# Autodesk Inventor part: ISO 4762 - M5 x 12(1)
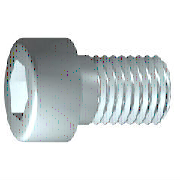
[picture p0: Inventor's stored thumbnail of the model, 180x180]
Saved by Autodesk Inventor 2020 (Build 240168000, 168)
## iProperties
Created: 2019-01
Part Number: ISO 4762 - M5 x 12(1)
Material: Nerezová ocel 440C
Description: Šroub s válcovou hlavou s vnitřním šestihranem
Document SubType Name: Modeling
Standard: ISO 4762
Designer: doma
Standard Revision: Fourth edition 2004-03-01
Standards Organization: ISO
Language: cs-CZ
Size Designation: M5 x 12
Categories: <MemberInstance><Categories><Category DisplayName="Spojovací materiál" InternalName="e4da775c-781d-43d5-af7c-5136215cf5a6" Mnemonic="FSTN"><Category DisplayName
Density: 7.75 g/cm^3
Appearance: Pololeštěná
IsCustomPart: 0
Author: doma
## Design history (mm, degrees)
sketch "Náčrt1"
  geometry: L1 (-1.167, 0)-(12, 0); L2 (12, 0)-(12, 2.5); L3 (12, 2.5)-(2, 2.5); L4 (2, 2.5)-(1.509, 2.5); L5 (1.509, 2.5)-(0, 2.5); L6 (0, 2.5)-(0, 4.25); L7 (0, 4.25)-(-5, 4.25); L8 (-5, 4.25)-(-5, 2.309); L9 (-5, 2.309)-(-2.5, 2.309); L10 (-2.5, 2.309)-(-1.167, 0); L11 (-8.4, 0)-(15.4, 0) reference; L12 (0, -0.85)-(0, 5.1) reference; L13 (2, 2.5)-(0, 2.5)
  constraints: 22 end point, 6 parallel, 2 collinear, 2 perpendicular, 1 horizontal, 1 point on line
  dimensions: "d1" = 10 distance from line of L3.end L2 (= GEL); "d2" = 0.49086 distance of L4.end L3.end (computed from GAL); "d3" = 5 distance between parallel lines of L8 L6 (= KOH); "d4" = 2.5 distance of L8.end L9.end (= INTI); "d5" = 60 deg angle of L10 L1; "d6" = 5 diameter of L3 L1 (= GD); "d7" = 5 diameter of L5 L1 (= BDM); "d8" = 4.6188 diameter of L9 L1 (= 1.1547 x SW); "d9" = 8.5 diameter of L7 L1 (= KOD); "d26" = 12 distance between parallel lines of L12 L2 (= NLG)
revolve "Těleso" sketch "Náčrt1" stored, may be unused: angle "d10" = 90 deg
sketch "Náčrt2"
  geometry: L1 (0, -5.95)-(0, 5.95) reference; L2 (-5.95, 0)-(5.95, 0) reference; L3 (2.309, 0)-(1.155, -2); L4 (1.155, -2)-(-1.155, -2); L5 (-1.155, -2)-(-2.309, 0); L6 (-2.309, 0)-(-1.155, 2); L7 (-1.155, 2)-(1.155, 2); L8 (1.155, 2)-(2.309, 0); 2 further points
  constraints: 12 end point, 1 coincident, 1 horizontal alignment, 1 point on line, 12 other
extrude "Drážka" join sketch "Náčrt2" stored distance "d11" = 10; taper "d12" = 0 deg
workplane "Work Plane1"
fillet "Fillet2" dims "d30" = 0.1 (= R)
body "Solid1"
fillet "Zaoblení1" dims "d17" = 0.5 (= RR)
feature "Závit" dims "d13" = 10 (= GEL), "d14" = 0
chamfer "Zkosení1" distance "d15" = 0.49076 (= -0.5 x SPD + 0.5 x GD); stored, may be unused: second distance "d16" = 0.49076 (= GUL), angle "d27" = 45 deg
other parameters: "GD" = 5 [user parameter; used in 2 equation terms], "NLG" = 12 [user parameter; used in 1 equation term], "GEL" = 10 [user parameter; used in 2 equation terms], "KOD" = 8.5 [user parameter; used in 1 equation term], "KOH" = 5 [user parameter; used in 1 equation term], "INTI" = 2.5 [user parameter; used in 1 equation term], "GAL" = 0.49076 (= 0.61345 x PTC) [user parameter; used in 1 equation term], "GUL" = 0.49076 (= 0.61345 x PTC) [user parameter; used in 1 equation term], "BDM" = 5 (= NND) [user parameter; used in 1 equation term], "SW" = 4 [user parameter; used in 2 equation terms], "RR" = 0.5 [user parameter; used in 1 equation term], "SPD" = 4.01848 (= NND - 1.2269 x PTC) [user parameter; used in 1 equation term], "d19" = 0, "d28" = 0, "d29" = 0, "R" = 0.1 [user parameter; used in 1 equation term], "TOA" = 30 deg [user parameter], "GD1" = 4.01848 (= THREADDIA - 1.2269 x PTC) [user parameter], "THREADDIA" = 5 [user parameter; used in 1 equation term], "FAWI" = 45 deg [user parameter], "TPU" = 12.5 (computed from PTC) [user parameter], "PTC" = 0.8 [user parameter; used in 5 equation terms], "NND" = 5 [user parameter; used in 2 equation terms], "E0" = 4.62 (= 1.155 x SW) [user parameter]
